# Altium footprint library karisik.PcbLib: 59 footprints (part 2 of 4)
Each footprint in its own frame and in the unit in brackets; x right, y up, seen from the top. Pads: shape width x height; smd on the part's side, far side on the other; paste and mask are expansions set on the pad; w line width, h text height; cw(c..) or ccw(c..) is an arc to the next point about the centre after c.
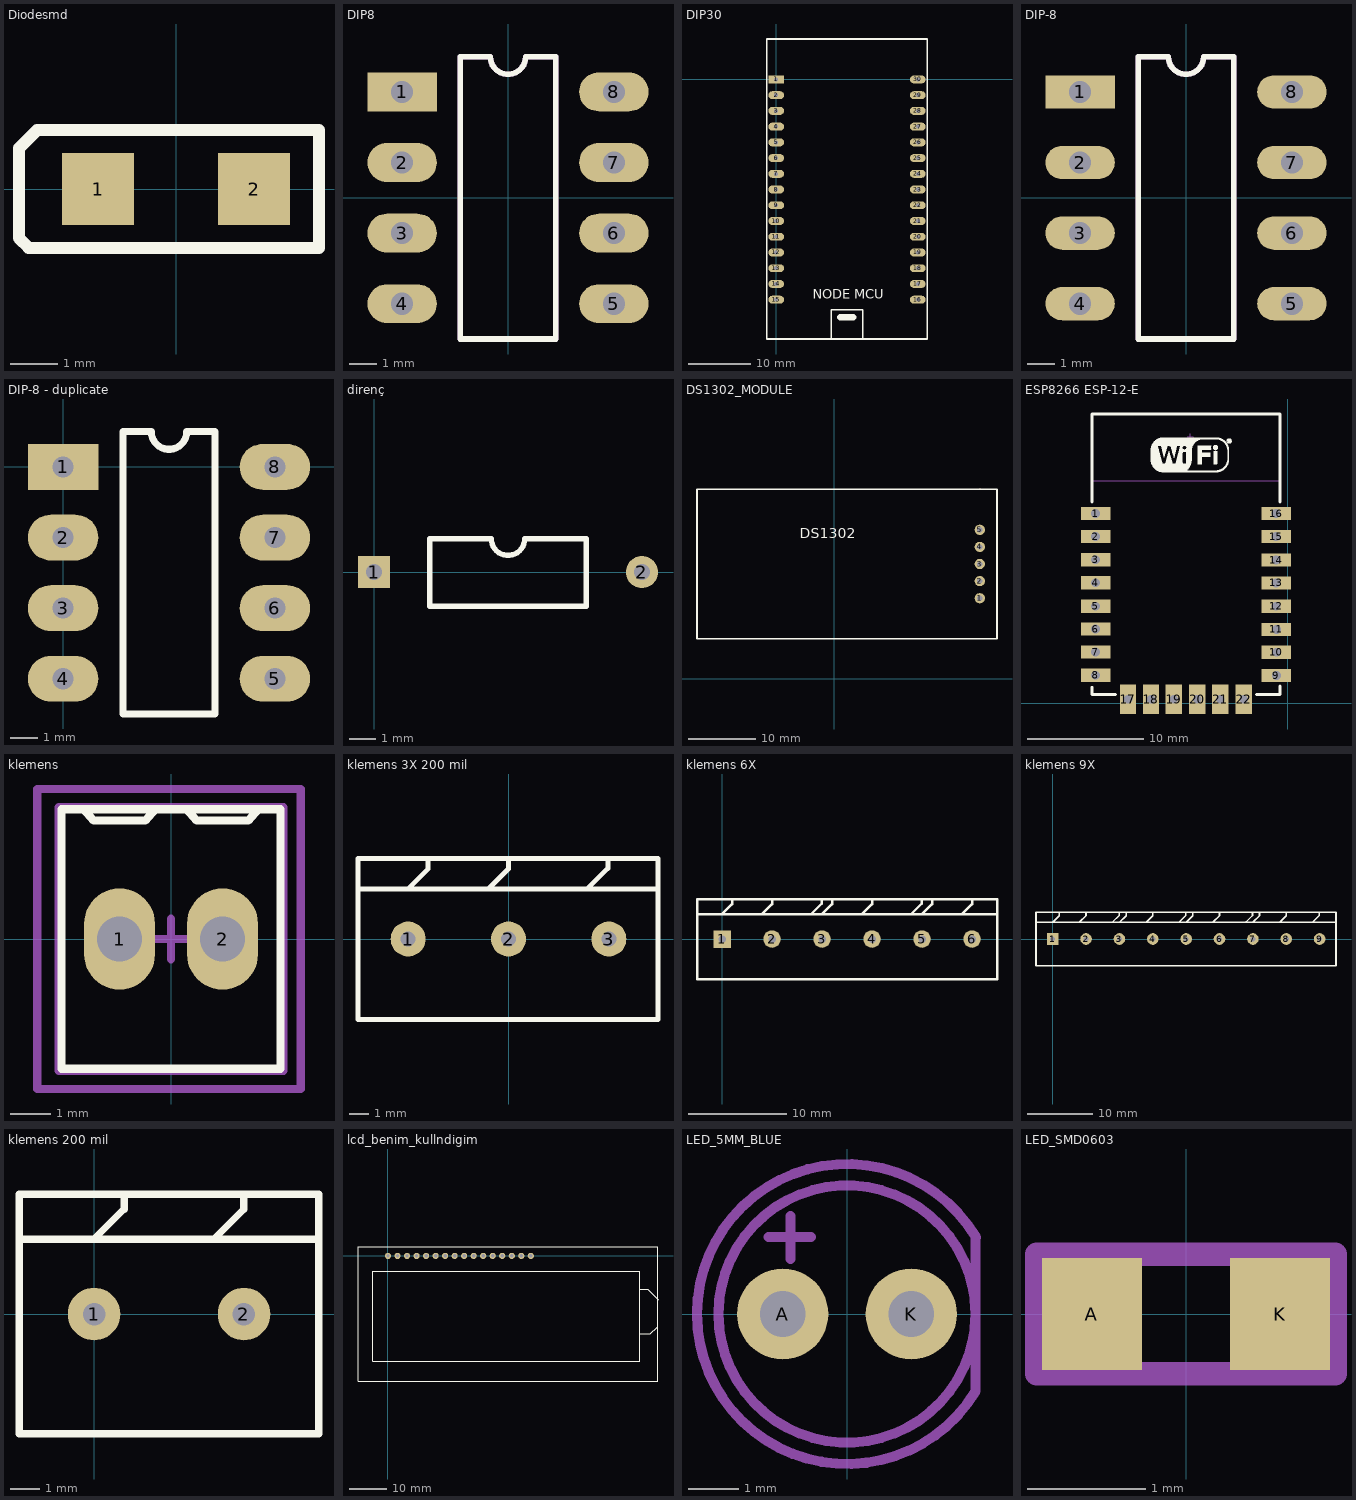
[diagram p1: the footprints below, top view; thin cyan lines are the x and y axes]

## Diodesmd [mil]
pads (2):
  rect 60x60 smd: 1(-65,0) 2(65,0)
Top Overlay:
  lines w10: -131,-41 -131,34 -116,49 119,49 119,-49 -123,-49 -131,-41

## DIP8 [mm]
pads (8):
  rect 2.5x1.4 hole 0.8: 1(-3.81,3.81)
  oval 2.5x1.4 hole 0.8: 2(-3.81,1.27) 3(-3.81,-1.27) 4(-3.81,-3.81) 5(3.81,-3.81) 6(3.81,-1.27) 7(3.81,1.27) 8(3.81,3.81)
Top Overlay:
  lines w0.2: -1.725,-5.08 1.725,-5.08 1.725,5.08 0.635,5.08 cw(c0,5.08) -0.635,5.08 -1.725,5.08 -1.725,-5.08
Mechanical 13:
  lines w0.2: -1.725,-5.08 1.725,-5.08 1.725,5.08 0.635,5.08 cw(c0,5.08) -0.635,5.08 -1.725,5.08 -1.725,-5.08
  text ".Designator" at -0.762,2.159 h2.5
3D body: height 3.5, standoff -1.81, extent -3.978,-4.75 3.937,4.75

## DIP30 [mil]
pads (30):
  rect 100x50 hole 25: 1(0,0)
  oval 100x50 hole 25: 2(0,-100) 3(0,-200) 4(0,-300) 5(0,-400) 6(0,-500) 7(0,-600) 8(0,-700) 9(0,-800) 10(0,-900) 11(0,-1000) 12(0,-1100) 13(0,-1200) 14(0,-1300) 15(0,-1400) 16(900,-1400) 17(900,-1300) 18(900,-1200) 19(900,-1100) 20(900,-1000) 21(900,-900) 22(900,-800) 23(900,-700) 24(900,-600) 25(900,-500) 26(900,-400) 27(900,-300) 28(900,-200) 29(900,-100) 30(900,0)
Top Overlay:
  lines w10: 349,-1650 349,-1465 549,-1465 549,-1649 ; -60,-1650 -60,257 474,257 960,257 960,-1650 -60,-1650
  lines w40: 407,-1512 489,-1512
  text "NODE MCU" at 232,-1395 h60

## DIP-8 [mm]
pads (8):
  rect 2.5x1.2 hole 0.8: 1(-3.81,3.81)
  oval 2.5x1.2 hole 0.8: 2(-3.81,1.27) 3(-3.81,-1.27) 4(-3.81,-3.81) 5(3.81,-3.81) 6(3.81,-1.27) 7(3.81,1.27) 8(3.81,3.81)
Top Overlay:
  lines w0.2: -1.725,-5.08 1.725,-5.08 1.725,5.08 0.635,5.08 cw(c0,5.08) -0.635,5.08 -1.725,5.08 -1.725,-5.08
Mechanical 13:
  lines w0.2: -1.725,-5.08 1.725,-5.08 1.725,5.08 0.635,5.08 cw(c0,5.08) -0.635,5.08 -1.725,5.08 -1.725,-5.08
  text ".Designator" at 0.127,-2.921 h1.52
3D body: height 6.08, standoff -2.5, extent -3.935,-5.46 3.935,5.46

## DIP-8 - duplicate [mil]
pads (8):
  rect 100x65 / inner rect 100x50 / far side rect 100x65 hole 30: 1(0,0)
  oval 100x65 / inner oval 100x50 / far side oval 100x65 hole 30: 2(0,-100) 3(0,-200) 4(0,-300) 5(300,-300) 6(300,-200) 7(300,-100) 8(300,0)
Top Overlay:
  lines w10: 85,-350 85,50 125,50 ccw(c150,50) 175,50 215,50 215,-350 85,-350

## direnç [mm]
height 1.8
pads (2):
  rect 1.2x1.2 hole 0.6: 1(0,0)
  round 1.2 hole 0.6: 2(10,0)
Top Overlay:
  lines w0.2: 2.085,-1.27 7.915,-1.27 7.915,1.25 5.625,1.25 cw(c5,1.25) 4.375,1.25 2.085,1.25 2.085,-1.27

## DS1302_MODULE [mil] "DS1302"
height 118.11
pads (5):
  round 60 hole 30: 1(852.5,470.45) 2(852.5,570.45) 3(852.5,670.45) 4(852.5,770.45) 5(852.5,870.45)
Top Layer:
  lines w10: 852,1107 852.22,1106.78 ; 852.22,870.73 852.5,870.45 853,870.95 ; 852.5,470.45 853,469.95
Top Overlay:
  lines w10: -801,234 953,234 953,1107 -801,1107 -801,234
  text "DS1302" at -199,822 h60

## ESP8266 ESP-12-E [mil] "ESP8266 ESP-12-E"
pads (22):
  rect 100x45 hole 30: 1(-653,646) 2(-653,568) 3(-653,489) 4(-653,411) 5(-653,331) 6(-653,253) 7(-653,175) 8(-653,96) 9(-38,95) 10(-38,174) 11(-38,252) 12(-39,331) 13(-39,410) 14(-39,488) 15(-39,568) 16(-39,646)
  rect 55x100 hole 30: 17(-543,14) 18(-465,14) 19(-387,14) 20(-307,14) 21(-229,14) 22(-149,14)
Top Overlay:
  drawing of 1267 lines, arcs and shapes, not listed
  text ".Designator" at -679,-84 h39.37
Mechanical 13:
  lines w2: -662.96,757.97 -22.96,757.97
  text "ANTENNA AREA" at -652.96,960.59 h10
  text "CUTOUT POLYGON" at -652.96,940.59 h10
Mechanical 15:
  lines w3.94: -341,907.92 -321,907.92 ; -331,897.92 -331,917.92
3D body: height 85.7, standoff -1.17, extent -661,36.56 -31.08,981.44

## klemens [mm]
height 10
pads (2):
  oval 1.75x2.5 hole 1.1: 1(-1.27,0) 2(1.27,0)
Top Overlay:
  lines w0.2: -2.159,3.2 -1.905,2.921 -0.635,2.921 -0.381,3.2 ; 0.381,3.2 0.635,2.921 1.905,2.921 2.159,3.2 ; -2.7,-3.2 -2.6,-3.2 2.7,-3.2 2.7,3.2 -2.7,3.2 -2.7,-3.2
Mechanical 13:
  lines w0.2: -2.77,-3.25 -2.77,3.25 2.77,3.25 2.77,-3.25 -2.77,-3.25
Mechanical 15:
  lines w0.2: -0.5,0 0.5,0 ; 0,-0.5 0,0.5 ; -3.3,-3.7 3.2,-3.7 3.2,-2.9 3.2,3.7 -3.3,3.7 -3.3,-3.3 -3.3,-3.7
3D body: height 10, standoff -3.4, extent -2.77,-3.25 2.77,3.25

## klemens 3X 200 mil [mil]
height 400
pads (3):
  round 70 hole 30: 1(-200,0) 2(0,0) 3(200,0)
Top Layer:
  lines w10: 0,0 1,1
Top Overlay:
  lines w10: -300,100 298,100 ; -200,100 -160,140 -160,160 ; -40,100 0,140 0,160 ; 159,102 198,141 198,154 ; -300,-160 298,-160 298,160 -300,160 -300,-160

## klemens 6X [mil]
height 400
pads (6):
  rect 70x70 hole 30: 1(0,0)
  round 70 hole 30: 2(200,0) 3(400,0) 4(600,0) 5(800,0) 6(1000,0)
Top Overlay:
  lines w10: -100,100 498,100 ; 0,100 40,140 40,160 ; 160,100 200,140 200,160 ; 300,-160 898,-160 ; 300,100 898,100 ; 300,160 898,160 ; 359,102 398,141 398,154 ; 400,100 440,140 440,160 ; 498,-160 -100,-160 -100,160 498,160 ; 560,100 600,140 600,160 ; 700,-160 1100,-160 1100,160 ; 700,100 1100,100 ; 700,160 1096,160 ; 759,102 798,141 798,154 ; 800,100 840,140 840,160 ; 960,100 1000,140 1000,160

## klemens 9X [mil]
height 400
pads (9):
  rect 70x70 hole 30: 1(0,0)
  round 70 hole 30: 2(200,0) 3(400,0) 4(600,0) 5(800,0) 6(1000,0) 7(1200,0) 8(1400,0) 9(1600,0)
Top Overlay:
  lines w10: -100,100 498,100 ; 0,100 40,140 40,160 ; 160,100 200,140 200,160 ; 300,-160 898,-160 ; 300,100 898,100 ; 300,160 898,160 ; 359,102 398,141 398,154 ; 400,100 440,140 440,160 ; 498,-160 -100,-160 -100,160 498,160 ; 560,100 600,140 600,160 ; 700,-160 1298,-160 ; 700,100 1298,100 ; 700,160 1298,160 ; 759,102 798,141 798,154 ; 800,100 840,140 840,160 ; 960,100 1000,140 1000,160 ; 1100,-160 1698,-160 1698,160 1100,160 ; 1100,100 1698,100 ; 1159,102 1198,141 1198,154 ; 1200,100 1240,140 1240,160 ; 1360,100 1400,140 1400,160 ; 1559,102 1598,141 1598,154

## klemens 200 mil [mil]
height 400
pads (2):
  round 70 hole 30: 1(0,0) 2(200,0)
Top Overlay:
  lines w10: -100,100 300,100 ; 0,100 40,140 40,160 ; 160,100 200,140 200,160 ; -100,-160 -100,160 300,160 300,145 300,80 300,-80 300,-160 -100,-160

## lcd_benim_kullndigim [mil]
pads (16):
  round 65 hole 35.43: 1(0,0) 2(100,0) 3(200,0) 4(300,0) 5(400,0) 6(500,0) 7(600,0) 8(700,0) 9(800,0) 10(900,0) 11(1000,0) 12(1100,0) 13(1200,0) 14(1300,0) 15(1400,0) 16(1500,0)
Top Overlay:
  lines w7.87: -314.96,-1318.9 2834.65,-1318.9 2834.65,98.43 -314.96,98.43 -314.96,-1318.9
  lines w10: 2643,-352 2730,-352 2836,-458 ; 2644,-820 2754,-820 2827,-747 ; 2646,-1109 -160,-1109 -160,-159 2646,-159 2646,-1108

## LED_5MM_BLUE [mm]
pads (2):
  round 1.8 hole 0.9: A(-1.27,0) K(1.27,0)
Mechanical 13:
  circle w0.2: c0,0 r2.54
  lines w0.2: -1.549,1.524 -0.711,1.524 ; -1.118,1.092 -1.118,1.93 ; 2.54,-1.525 2.54,1.506 ; 2.542,-1.525 cw(c0,0) 2.55,1.512
  text ".Designator" at -2.108,3.429 h1.5
3D body: height 12.31, standoff -2.49, extent -2.98,-3.01 2.44,3.01

## LED_SMD0603 [mm] "Chip Resistor, 2-Leads, Body 1,6x0,8mm, IPC Medium Density"
height 0.9
pads (2):
  rect 0.85x0.95 smd: A(-0.8,0) K(0.8,0)
Mechanical 13:
  lines w0.2: -1.27,-0.508 -1.27,0.508 1.27,0.508 1.27,-0.508 -1.27,-0.508
  text ".Designator" at -1.016,-0.305 h1
3D body: height 0.68, standoff 0, extent -0.825,-0.381 0.825,0.344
